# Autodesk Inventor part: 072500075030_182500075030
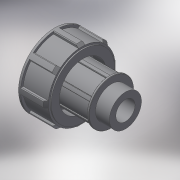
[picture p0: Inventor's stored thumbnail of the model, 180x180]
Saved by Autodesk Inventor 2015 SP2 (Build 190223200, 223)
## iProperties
Created: 2017-04
Part Number: 072500075030_182500075030
Material: Generic
Description: PLASSON THREADED ADAPTOR 75-3"
Document SubType Name: Modeling
Designer: KIM
Density: 1 g/cm^3
Appearance: Default
Author: KIM
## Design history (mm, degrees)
derived "07250.ipt"
feature "Solid1::07250.ipt"
tag "TaggingFeature1"
body "Solid1"
other parameters: "d1" = 87.884, "d2" = 137, "d3" = 33, "d6" = 132, "d7" = 122.76, "d8" = 105.6, "d9" = 75, "d10" = 96.6724, "d12" = 52.7304, "d13" = 61.5188, "d14" = 37.95, "d15" = 99, "d16" = 4.11, "d17" = 54.8, "d18" = 33, "d19" = 39.6, "d24" = 17.5768, "d25" = 8.7884, "d27" = 0, "d28" = 7.03072, "d31" = 1.75768, "d35" = 360 deg, "d41" = 29.337, "d56" = 82.5, "d57" = 7.5, "d58" = 3.75, "d60" = 0, "d61" = 0.87884, "d64" = 0.87884, "d68" = 360 deg, "d_" = 75, "R_" = 87.884, "E_" = 132, "H_" = 137, "l_2" = 33, "d55" = 75
